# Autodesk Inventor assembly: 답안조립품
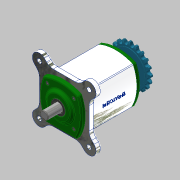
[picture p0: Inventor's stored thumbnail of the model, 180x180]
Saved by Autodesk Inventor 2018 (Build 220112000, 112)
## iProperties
Created: 2022-01
Part Number: 답안조립품
Material: 일반
Document SubType Name: Assembly
Designer: home
Author: home
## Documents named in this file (13)
- C:\Users\kimgi\Desktop\720106V1023\답안조립품.iam
- C:\Users\kimgi\Desktop\720106V1023\본체.ipt
- C:\Users\kimgi\Desktop\720106V1023\베어링 6203.ipt
- C:\Users\kimgi\Desktop\720106V1023\커버.ipt
- C:\Users\kimgi\Desktop\720106V1023\편심축.ipt
- C:\Users\kimgi\Desktop\720106V1023\오일 실 17 x 30 x 8.ipt
- C:\Users\kimgi\Desktop\720106V1023\키 5 x 5.ipt
- C:\Users\kimgi\Desktop\720106V1023\스프로킷.ipt
- C:\Users\kimgi\Desktop\720106V1023\와셔 4 x 20.ipt
- C:\Users\kimgi\Desktop\720106V1023\육각머리볼트 M4.ipt
- C:\Users\kimgi\Desktop\720106V1023\부시.ipt
- C:\Users\kimgi\Desktop\720106V1023\슬라이더.ipt
- C:\Users\kimgi\Desktop\720106V1023\볼트 M4 x 12.ipt
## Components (8 placed, 1 different names)
1. M4x0.7x12:2
2. M4x0.7x12:3
3. M4x0.7x12:4
4. M4x0.7x12:5
5. M4x0.7x12:1
6. M4x0.7x12:6
7. M4x0.7x12:7
8. M4x0.7x12:8
